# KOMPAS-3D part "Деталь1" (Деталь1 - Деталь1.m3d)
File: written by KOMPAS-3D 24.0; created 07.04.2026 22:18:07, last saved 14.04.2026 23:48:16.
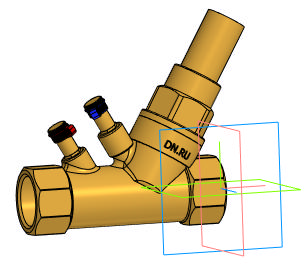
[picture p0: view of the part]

Document properties: Автор: tyuri; Полное имя файла: D:\Аутсорс\VB0000P-T Клапан балансировочный статический DN.ru\DN20\Исходные файлы\Деталь1 - Деталь1.m3d

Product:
- Body: Твердое тело1  | qty 1
- Part/product: Деталь1
    additional columns: Типовые

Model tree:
1. Твердое тело1  (labels: Твердое тело1)
2. Изменить положение граней:1  (labels: Грань.Твердое тело1)
     Расстояние = 2
3. Изменить положение граней:2  (labels: Грань.Твердое тело1)
     Расстояние = 2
